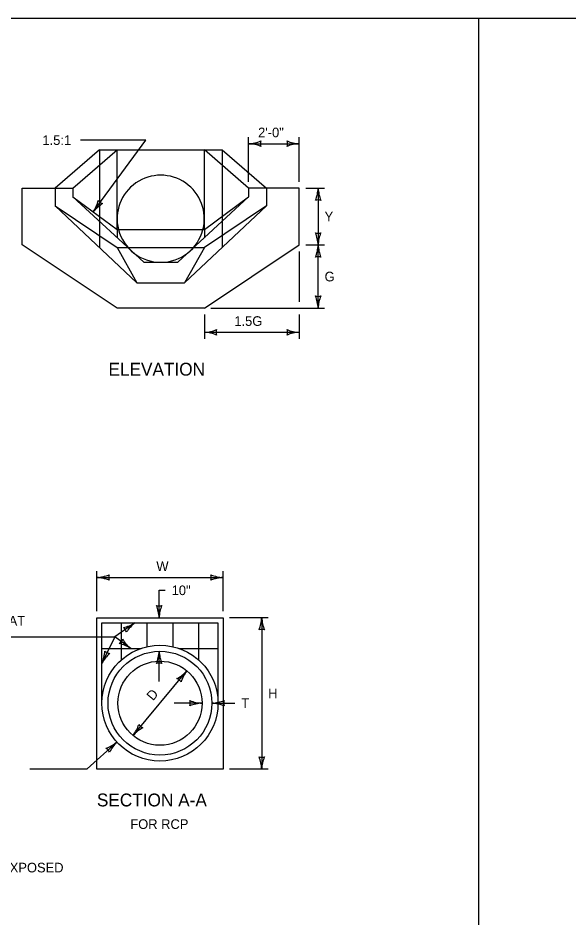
# Model space of a CAD drawing. Extents: x 49991.4 to 50043, y 49987.6 to 50011.4.
# Drawn here: x 50005.2 to 50008.63, y 49993.4 to 49999 of the extents above; entities that cross this region are included whole.
import ezdxf

# ---------------------------------------------------------------- set-up
doc = ezdxf.new("R2010")
doc.units = 0
for name, color, linetype in [('Level 1', 7, 'Continuous'), ('Level 2', 7, 'Continuous'), ('Level 3', 7, 'Continuous'), ('Level 4', 7, 'Continuous')]:
    doc.layers.add(name, color=color, linetype=linetype)

msp = doc.modelspace()

# ---------------------------------------------------------------- linework, layer by layer
at = {"layer": 'Level 1'}
for p, q in [((50008.0668, 49998.9992), (50008.0668, 49987.7988)), ((50005.7099, 49998.1783), (50005.4347, 49997.9407)), ((50005.5448, 49997.9407), (50005.8201, 49998.1783)), ((50005.7099, 49998.1783), (50006.4723, 49998.1783)), ((50005.8201, 49997.6834), (50005.8201, 49998.1783)), ((50006.3621, 49997.6834), (50006.3621, 49998.1783)), ((50006.6375, 49997.9407), (50006.3621, 49998.1783)), ((50006.4723, 49998.1783), (50006.7476, 49997.9407)), ((50005.2302, 49997.5868), (50005.2302, 49997.9407)), ((50005.2302, 49997.9407), (50005.5448, 49997.9407)), ((50005.5448, 49997.9407), (50005.5448, 49997.8856)), ((50006.9521, 49997.9407), (50006.6375, 49997.9407)), ((50006.6375, 49997.9407), (50006.6375, 49997.8856)), ((50006.9521, 49997.5868), (50006.9521, 49997.9407)), ((50005.5448, 49997.8856), (50005.8201, 49997.6834)), ((50006.3621, 49997.6834), (50006.6375, 49997.8856)), ((50005.8201, 49997.6834), (50006.3621, 49997.6834)), ((50005.8201, 49997.1935), (50005.2302, 49997.5868)), ((50006.3621, 49997.1935), (50006.9521, 49997.5868)), ((50006.3621, 49997.1935), (50005.8201, 49997.1935)), ((50005.6937, 49995.2678), (50006.4788, 49995.2678)), ((50005.6937, 49994.3256), (50005.6937, 49995.2678)), ((50005.7256, 49995.236), (50006.447, 49995.236)), ((50005.7256, 49994.7356), (50005.7256, 49995.236)), ((50005.8444, 49995.236), (50005.8444, 49995.0032)), ((50006.0052, 49995.236), (50006.0052, 49995.0871)), ((50006.166, 49995.236), (50006.166, 49995.0874)), ((50006.3267, 49995.236), (50006.3267, 49995.0045)), ((50006.447, 49995.236), (50006.447, 49994.7356)), ((50006.4788, 49995.2678), (50006.4788, 49994.3256)), ((50005.7256, 49995.0752), (50005.9648, 49995.0752)), ((50006.2078, 49995.0752), (50006.447, 49995.0752)), ((50006.4788, 49994.3256), (50005.6937, 49994.3256))]:
    msp.add_line(p, q, dxfattribs=at)
msp.add_lwpolyline([(49999.3835, 49998.9992), (50016.7501, 49998.9992), (50016.7501, 49987.7988), (49999.3835, 49987.7988)], close=True, dxfattribs=at)
for radius in [0.3607, 0.3228, 0.2617]:
    msp.add_circle((50006.0863, 49994.7356), radius, dxfattribs=at)
msp.add_arc((50006.0911, 49997.75), 0.271, 345.7745, 194.2255, dxfattribs=at)
at = {"layer": 'Level 3'}
for p, q in [((50006.6375, 49997.9807), (50006.6375, 49998.2571)), ((50006.9521, 49997.9807), (50006.9521, 49998.2571)), ((50005.9989, 49998.239), (50005.5926, 49998.239)), ((50005.6715, 49997.7925), (50005.9989, 49998.239)), ((50006.6375, 49998.2171), (50006.9521, 49998.2171)), ((50006.9921, 49997.9407), (50007.1095, 49997.9407)), ((50007.0695, 49997.9407), (50007.0695, 49997.5868)), ((50006.9921, 49997.5868), (50007.1095, 49997.5868)), ((50007.0695, 49997.1935), (50007.0695, 49997.5868)), ((50006.9521, 49997.5468), (50006.9521, 49997.2335)), ((50006.4021, 49997.1935), (50007.1095, 49997.1935)), ((50006.3621, 49997.1535), (50006.3621, 49997.0034)), ((50006.9521, 49997.1535), (50006.9521, 49997.0034)), ((50006.3621, 49997.0434), (50006.9521, 49997.0434)), ((50005.6937, 49995.3078), (50005.6937, 49995.5576)), ((50005.6937, 49995.5176), (50006.4788, 49995.5176)), ((50006.4788, 49995.3078), (50006.4788, 49995.5576)), ((50006.0812, 49995.2678), (50006.0812, 49995.4381)), ((50006.0812, 49995.4381), (50006.1189, 49995.4381)), ((50005.931, 49995.236), (50005.8063, 49995.1488)), ((50006.7588, 49995.2678), (50006.5188, 49995.2678)), ((50006.7188, 49995.2678), (50006.7188, 49994.3256)), ((50005.1614, 49995.1487), (50005.8063, 49995.1488)), ((50005.8063, 49995.1488), (50005.7256, 49994.9843)), ((50005.9047, 49995.0752), (50005.8063, 49995.1488)), ((50006.0812, 49994.871), (50006.0812, 49995.0584)), ((50005.9189, 49994.5344), (50006.2536, 49994.9368)), ((50006.348, 49994.7356), (50006.1746, 49994.7356)), ((50006.4091, 49994.7356), (50006.5517, 49994.7356)), ((50005.6347, 49994.3266), (50005.8183, 49994.4941)), ((50005.2782, 49994.3266), (50005.6347, 49994.3266)), ((50006.7588, 49994.3256), (50006.5188, 49994.3256))]:
    msp.add_line(p, q, dxfattribs=at)
for centre, radius, start, end in [((50006.626, 49998.4498), 0.233, 272.8273, 292.0772), ((50006.6283, 49997.995), 0.2223, 67.456, 87.6395), ((50006.7657, 49998.2171), 0.0548, 162.1388, 197.8612), ((50006.9613, 49998.4393), 0.2223, 247.456, 267.6395), ((50006.8239, 49998.2171), 0.0548, 342.1388, 17.8612), ((50006.9636, 49997.9844), 0.233, 92.8273, 112.0772), ((50006.8474, 49997.9499), 0.2223, 337.456, 357.6395), ((50007.3022, 49997.9522), 0.233, 182.8273, 202.0772), ((50005.4772, 49997.921), 0.233, 326.5303, 345.7801), ((50005.7474, 49997.8959), 0.0548, 215.8418, 251.5642), ((50007.0695, 49997.8125), 0.0548, 72.1388, 107.8612), ((50005.8451, 49997.6537), 0.2223, 121.159, 141.3425), ((50007.0695, 49997.715), 0.0548, 252.1388, 287.8612), ((50006.8368, 49997.5753), 0.233, 2.8273, 22.0772), ((50007.2916, 49997.5777), 0.2223, 157.456, 177.6395), ((50006.8474, 49997.596), 0.2223, 337.456, 357.6395), ((50007.3022, 49997.5983), 0.233, 182.8273, 202.0772), ((50007.0695, 49997.4586), 0.0548, 72.1388, 107.8612), ((50007.0695, 49997.3217), 0.0548, 252.1388, 287.8612), ((50006.8368, 49997.182), 0.233, 2.8273, 22.0772), ((50007.2916, 49997.1844), 0.2223, 157.456, 177.6395), ((50006.3506, 49997.2761), 0.233, 272.8273, 292.0772), ((50006.3529, 49996.8213), 0.2223, 67.456, 87.6395), ((50006.4903, 49997.0434), 0.0548, 162.1388, 197.8612), ((50006.9613, 49997.2656), 0.2223, 247.456, 267.6395), ((50006.8239, 49997.0434), 0.0548, 342.1388, 17.8612), ((50006.9636, 49996.8107), 0.233, 92.8273, 112.0772), ((50005.6822, 49995.7503), 0.233, 272.8273, 292.0772), ((50005.6845, 49995.2955), 0.2223, 67.456, 87.6395), ((50005.8219, 49995.5176), 0.0548, 162.1388, 197.8612), ((50006.488, 49995.7398), 0.2223, 247.456, 267.6395), ((50006.3506, 49995.5176), 0.0548, 342.1388, 17.8612), ((50006.4903, 49995.2849), 0.233, 92.8273, 112.0772), ((50006.0812, 49995.396), 0.0548, 252.1388, 287.8612), ((50005.8485, 49995.2563), 0.233, 2.8273, 22.0772), ((50006.3033, 49995.2587), 0.2223, 157.456, 177.6395), ((50005.8112, 49995.4233), 0.2223, 282.4274, 302.6109), ((50006.0738, 49995.0519), 0.233, 127.7987, 147.0485), ((50006.4967, 49995.277), 0.2223, 337.456, 357.6395), ((50006.9515, 49995.2793), 0.233, 182.8273, 202.0772), ((50005.8259, 49995.1625), 0.0548, 17.1102, 52.8325), ((50006.7188, 49995.1396), 0.0548, 72.1388, 107.8612), ((50005.802, 49995.152), 0.0548, 305.349, 341.0713), ((50006.0451, 49995.2476), 0.2223, 210.6662, 230.8497), ((50005.5116, 49995.0765), 0.233, 336.6993, 355.9492), ((50005.782, 49995.0994), 0.0548, 226.0108, 261.7332), ((50005.7745, 49994.882), 0.233, 56.0375, 75.2873), ((50005.8591, 49995.0676), 0.2223, 337.456, 357.6395), ((50006.3139, 49995.0699), 0.233, 182.8273, 202.0772), ((50005.921, 49994.8783), 0.2223, 131.328, 151.5115), ((50006.0812, 49994.9302), 0.0548, 72.1388, 107.8612), ((50006.0887, 49995.0859), 0.2223, 297.7037, 317.8872), ((50006.4399, 49994.7969), 0.233, 143.075, 162.3249), ((50006.1716, 49994.8383), 0.0548, 32.3865, 68.1089), ((50006.3572, 49994.9578), 0.2223, 247.456, 267.6395), ((50006.2198, 49994.7356), 0.0548, 342.1388, 17.8612), ((50006.3595, 49994.5029), 0.233, 92.8273, 112.0772), ((50006.3981, 49994.9684), 0.233, 272.7247, 291.9746), ((50006.3996, 49994.5135), 0.2223, 67.3534, 87.5369), ((50006.5373, 49994.7354), 0.0548, 162.0362, 197.7586), ((50005.7326, 49994.6744), 0.233, 323.075, 342.3249), ((50006.0838, 49994.3853), 0.2223, 117.7037, 137.8872), ((50006.0009, 49994.633), 0.0548, 212.3865, 248.1089), ((50005.6753, 49994.6643), 0.2223, 289.8633, 310.0468), ((50005.7236, 49994.4077), 0.0548, 24.5461, 60.2684), ((50005.9837, 49994.3301), 0.233, 135.2346, 154.4844), ((50006.7188, 49994.4538), 0.0548, 252.1388, 287.8612), ((50006.4861, 49994.3141), 0.233, 2.8273, 22.0772), ((50006.9409, 49994.3165), 0.2223, 157.456, 177.6395)]:
    msp.add_arc(centre, radius, start, end, dxfattribs=at)
at = {"layer": 'Level 4'}
for p, q in [((50005.7099, 49998.1783), (50005.7099, 49997.5711)), ((50006.4723, 49998.1783), (50006.4723, 49997.571)), ((50005.4347, 49997.9407), (50005.4347, 49997.8305)), ((50006.7476, 49997.9407), (50006.7476, 49997.8305)), ((50005.9851, 49997.479), (50005.5448, 49997.8856)), ((50006.1971, 49997.479), (50006.6375, 49997.8856)), ((50005.4347, 49997.8305), (50005.9435, 49997.3508)), ((50005.4347, 49997.8305), (50005.8201, 49997.571)), ((50006.7476, 49997.8305), (50006.2386, 49997.3508)), ((50006.7476, 49997.8305), (50006.3621, 49997.571)), ((50005.8201, 49997.6834), (50005.8201, 49997.6314)), ((50006.3621, 49997.6834), (50006.3621, 49997.6313)), ((50005.8201, 49997.571), (50006.3621, 49997.571)), ((50005.8201, 49997.571), (50005.9435, 49997.3508)), ((50006.3621, 49997.571), (50006.2386, 49997.3508)), ((50005.9851, 49997.479), (50006.1971, 49997.479)), ((50005.9435, 49997.3508), (50006.2386, 49997.3508))]:
    msp.add_line(p, q, dxfattribs=at)
msp.add_arc((50006.0911, 49997.75), 0.271, 194.2255, 345.7745, dxfattribs=at)

# ---------------------------------------------------------------- texts
at = {"layer": 'Level 2'}
for s, height, p in [('2\'-0"', 0.06, (50006.6963, 49998.2571)), ('1.5:1', 0.06, (50005.3558, 49998.209)), ('Y', 0.06, (50007.1095, 49997.7338)), ('G', 0.06, (50007.1095, 49997.3602)), ('1.5G', 0.06, (50006.5485, 49997.0834)), ('ELEVATION', 0.08, (50005.7661, 49996.7738)), ('W', 0.06, (50006.064, 49995.5576)), ('10"', 0.06, (50006.1589, 49995.4081)), ('#4 BARS AT ', 0.06, (50004.7934, 49995.2187)), ('H', 0.06, (50006.7588, 49994.7667)), ('T', 0.06, (50006.5917, 49994.7056)), ('SECTION A-A', 0.08, (50005.6943, 49994.0933)), ('FOR RCP', 0.06, (50005.902, 49993.9533)), ('CHAMFER ALL EXPOSED', 0.06, (50004.515, 49993.6827))]:
    msp.add_text(s, height=height, dxfattribs=at).set_placement(p)
msp.add_text('D', height=0.06, rotation=50.2561, dxfattribs=at).set_placement((50006.0436, 49994.7469))

doc.saveas('drawing.dxf')
